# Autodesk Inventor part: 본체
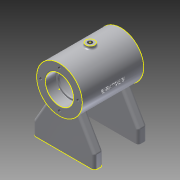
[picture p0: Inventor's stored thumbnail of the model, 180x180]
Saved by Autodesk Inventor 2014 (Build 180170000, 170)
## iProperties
Created: 2018-05
Part Number: 본체
Material: 알루미늄 6061
Document SubType Name: Modeling
Designer: 602-17
Density: 2.71 g/cm^3
Appearance: 알루미늄 - 평지
Author: 602-17
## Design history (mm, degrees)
sketch "스케치1"
  geometry: L1 (-35, 0)-(-35, 26); L2 (-35, 26)-(35, 26); L3 (35, 26)-(35, 0); L4 (35, 0)-(-35, 0); 1 further point
  constraints: 8 end point, 2 parallel, 1 perpendicular, 1 vertical
  dimensions: "d0" = 26 distance of L1.start L1.end; "d1" = 70 distance of L1.end L2.end; "d2" = 35 distance from line of point (0, 0) L1
revolve "회전1" sketch "스케치1" stored, may be unused: angle "d3" = 90 deg
sketch "스케치2"
  geometry: L1 (-35, 0)-(-35, 16); L2 (-35, 16)-(-23, 16); L3 (-23, 16)-(-23, 14); L4 (-23, 14)-(-21, 14); L5 (-21, 14)-(-21, 21); L6 (-21, 21)-(21, 21); L7 (21, 21)-(21, 14); L8 (21, 14)-(23, 14); L9 (23, 14)-(23, 16); L10 (23, 16)-(35, 16); L11 (35, 16)-(35, 0); L12 (35, 0)-(-35, 0); L13 (-35, -26)-(-35, 26) reference; 1 further point
  constraints: 24 end point, 9 parallel, 1 collinear, 1 midpoint, 1 perpendicular, 1 vertical
  dimensions: "d4" = 32 diameter of L2 L12; "d5" = 42 diameter of L6 L12; "d6" = 32 diameter of L10 L12; "d7" = 28 diameter of L8 L12; "d8" = 28 diameter of L4 L12; "d9" = 12 distance of L1.end L2.end; "d10" = 42 distance of L5.end L6.end; "d11" = 12 distance of L9.end L10.end; "d12" = 2 distance of L3.end L4.end; "d13" = 2 distance of L7.end L8.end
sketch "스케치3"
  geometry: 1 further point
revolve "회전2" stored, may be unused: angle "d14" = 90 deg
fillet "모깎기1" dims "d15" = 0.3
sketch "스케치4"
  geometry: 1 further point
fillet "모깎기2" dims "d16" = 3
fillet "모깎기3" dims "d17" = 3
node "작업 평면1"
sketch "스케치5"
  geometry: C1 r 5 at (0, 0); 1 further point
  constraints: 1 centre point, 1 coincident
  dimensions: "d19" = 10 diameter of C1
extrude "돌출1" join sketch "스케치5" stored distance "d20" = 10; taper "d21" = 0 deg
sketch "스케치6"
  geometry: C1 r 5 at (0, 0) reference
hole "구멍1" diameter "d24" = 5.188; stored, may be unused: countersink angle "d28" = 90 deg, drill point angle "d30" = 118 deg; dims "d22" = 10, "d23" = 10, "d25" = 6, "d26" = 4, "d27" = 2, "d29" = 8
fillet "모깎기4" dims "d31" = 2
node "작업 평면5"
sketch "스케치11"
  geometry: L1 (17.325, -19.386)-(35, -50); L2 (35, -50)-(35, -65); L3 (35, -65)-(0, -65); L4 (0, -65)-(0, -26); A1 r 26 centre (0, 0) between (17.325, -19.386) and (0, -26) reference; 1 further point
  constraints: 8 end point, 2 perpendicular, 2 point on circle, 1 vertical, 1 vertical alignment
  dimensions: "d49" = 30 deg angle of L2 L1; "d50" = 15 distance of L1.end L2.end; "d51" = 35 distance of L2.end L3.end; "d52" = 65 distance of L3.end point (0, 0)
extrude "돌출3" join sketch "스케치11" stored distance "d53" = 10; taper "d54" = 0 deg
fillet "모깎기5" dims "d55" = 3
sketch "스케치12"
  geometry: C1 r 16 at (0, 0) reference; C2 r 26 at (0, 0) reference
sketch "스케치13"
  geometry: L1 (0, 0)-(0, 21.135); L2 (0, 21.135)-(0, -4.865); C1 r 26 at (0, 0) reference; 1 further point
  constraints: 4 end point, 1 coincident, 1 collinear, 1 vertical
  dimensions: "d56" = 26 distance of L1.end L2.end
hole "구멍2" sketch "스케치13" at (0, 21.135) diameter "d57" = 3.242; stored, may be unused: countersink angle "d61" = 90 deg, drill point angle "d63" = 118 deg; dims "d58" = 8, "d59" = 4, "d60" = 2, "d62" = 10
sketch "스케치14"
  geometry: L1 (67, -7)-(67, -3) reference; L2 (64, 0)-(0, 0) reference; L3 (-3, -7)-(-3, -3) reference; L4 (64, -10)-(0, -10) reference; A1 r 3 centre (64, -7) between (64, -10) and (67, -7) reference; A2 r 3 centre (64, -3) between (67, -3) and (64, 0) reference; A3 r 3 centre (0, -3) between (0, 0) and (-3, -3) reference; A4 r 3 centre (0, -7) between (-3, -7) and (0, -10) reference; 1 further point
sketch "스케치15"
  geometry: L1 (64, 0)-(0, 0) reference; L2 (64, -10)-(0, -10) reference; L3 (12, -5)-(32, -5); 2 further points
  constraints: 2 end point, 2 parallel, 1 coincident, 1 vertical alignment
  dimensions: "d67" = 25 distance from line of L3 point (32, 20); "d68" = 20 distance of L3.start L3.end
hole "구멍3" sketch "스케치15" at (12, -5) diameter "d69" = 4.134; stored, may be unused: countersink angle "d73" = 90 deg, drill point angle "d75" = 118 deg; dims "d70" = 8, "d71" = 4, "d72" = 2, "d74" = 10
sketch "스케치16"
  geometry: 1 further point
sketch "스케치17"
  geometry: C1 r 1.621 at (21.135, 0) reference; C2 r 1.621 at (0, 21.135) reference; C3 r 1.621 at (-21.135, 0) reference; C4 r 1.621 at (0, -21.135) reference; C5 r 16 at (0, 0) reference; C6 r 26 at (0, 0) reference
sketch "스케치18"
  geometry: 1 further point
node "작업 평면6"
sketch "스케치19"
  geometry: L1 (-13.993, 4.518)-(14.284, 4.518); L2 (14.284, 4.518)-(14.284, -5.101); L3 (14.284, -5.101)-(-13.993, -5.101); L4 (-13.993, -5.101)-(-13.993, 4.518); 1 further point
  constraints: 2 other
feature "엠보싱1" sketch "스케치19" dims "d0" = 26, "d1" = 70, "d2" = 35, "d12" = 2, "d77" = 1, "d78" = 0
fillet "모깎기6" dims "d79" = 1
node "솔리드1"
mirror "대칭1"
mirror "대칭2"
pattern_circular "원형 패턴1" dims angle "d65" = 360 deg
mirror "대칭3"
mirror "대칭4"
mirror "대칭5"
mirror "대칭6"
other parameters: "d18" = 29, "d48" = -25, "d76" = 26
